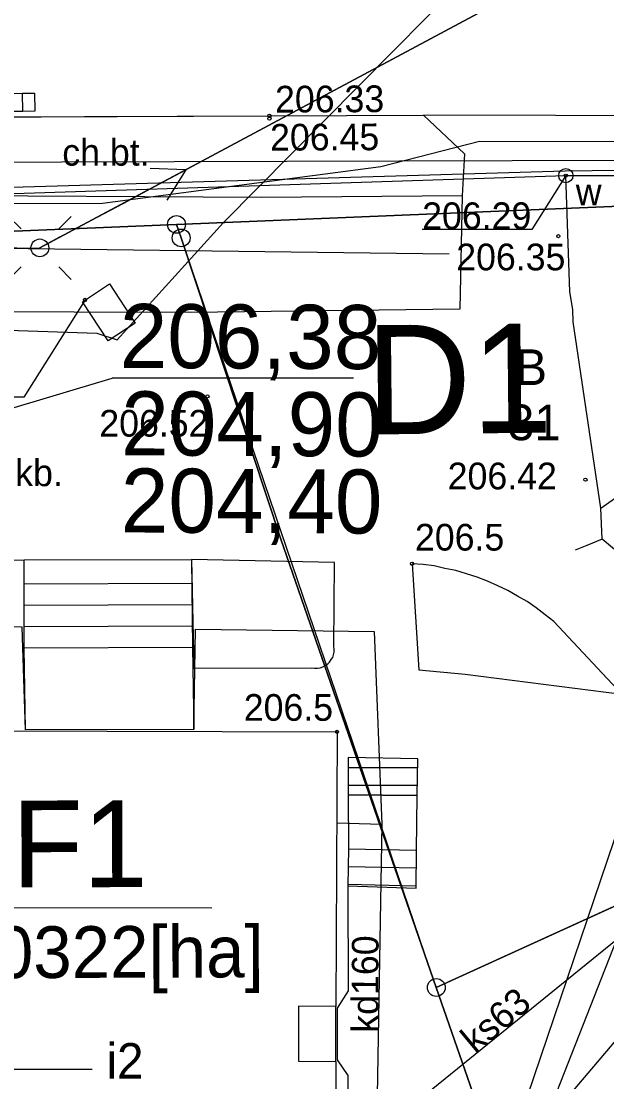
# Model space of a CAD drawing. Extents: x 6512606 to 6513006, y 6022524 to 6022728.
# Drawn here: x 6512750.51 to 6512766.96, y 6022649.64 to 6022679.43 of the extents above; entities that cross this region are included whole.
import ezdxf

# ---------------------------------------------------------------- set-up
doc = ezdxf.new("R2010")
doc.units = 0
for name, color, linetype in [('20', 7, 'Continuous'), ('202-punkt graniczny', 7, 'Continuous'), ('210-oznaczenie konturu użytku gruntowego', 7, 'Continuous'), ('211-numer działki ewidencyjnej', 7, 'Continuous'), ('216-obręb ewidencyjny', 7, 'Continuous'), ('218-kontur użytku gruntowego', 7, 'Continuous'), ('219-działka ewidencyjna', 7, 'Continuous'), ('312-budynek ewidencyjny', 7, 'Continuous'), ('312-oznaczenie budynku ewidencyjnego-Atr117', 7, 'Continuous'), ('352-schody', 7, 'Continuous'), ('4', 7, 'Continuous'), ('chodnik', 7, 'Continuous'), ('chodnik (powierzchnia)', 7, 'Continuous'), ('chodnik (powierzchnia)-Atr17', 7, 'Continuous'), ('chodnik-Atr17', 7, 'Continuous'), ('Default', 7, 'Continuous'), ('inny obiekt zagospodarowania terenu', 7, 'Continuous'), ('jezdnia (powierzchnia)', 7, 'Continuous'), ('komora podziemna - przewód kanalizacyjny (powierzchnia)', 7, 'Continuous'), ('kratka ściekowa (punkt)', 7, 'Continuous'), ('krawężnik (linia)', 7, 'Continuous'), ('latarnia na słupie lub maszcie (punkt)', 7, 'Continuous'), ('Level 47', 7, 'Continuous'), ('maxp_inst_wodociągowa', 7, 'Continuous'), ('maxp_opisy', 7, 'Continuous'), ('pikieta sztuczna', 7, 'Continuous'), ('pikieta sztuczna-Atr2', 7, 'Continuous'), ('przewód elektroenergetyczny (linia)', 7, 'Continuous'), ('przewód elektroenergetyczny niskiego napięcia (linia)', 7, 'Continuous'), ('przewód elektroenergetyczny niskiego napięcia (linia) - symbol', 7, 'Continuous'), ('przewód gazowy (linia)', 7, 'Continuous'), ('przewód kanalizacyjny (linia)', 7, 'Continuous'), ('przewód kanalizacyjny (linia)-Atr1', 7, 'Continuous'), ('przewód wodociągowy (linia)', 7, 'Continuous'), ('punkt o określonej wysokości (sieć kanalizacyjna)', 7, 'Continuous'), ('punkt o określonej wysokości (sieć kanalizacyjna)-Atr2', 7, 'Continuous'), ('punkt o określonej wysokości (sieć wodociągowa)', 7, 'Continuous'), ('punkt o określonej wysokości (sieć wodociągowa)-Atr2', 7, 'Continuous'), ('punkt wysokościowy naturalny', 7, 'Continuous'), ('punkt wysokościowy naturalny-Atr2', 7, 'Continuous'), ('punkt wysokościowy sztuczny', 7, 'Continuous'), ('punkt wysokościowy sztuczny-Atr2', 7, 'Continuous'), ('schody w ciągu komunikacyjnym', 7, 'Continuous'), ('słup (punkt)', 7, 'Continuous'), ('zasuwa - siec wodociągowa (punkt)', 7, 'Continuous'), ('zasuwa - siec wodociągowa (punkt)-Atr17', 7, 'Continuous')]:
    doc.layers.add(name, color=color, linetype=linetype)

# ---------------------------------------------------------------- blocks, each defined once
blk = doc.blocks.new('202')
at = {"layer": 'Default'}
blk.add_circle((0, 0), 2.5, dxfattribs=at)
blk = doc.blocks.new('PE04')
at = {"layer": 'Default'}
for p, q in [((46.5, 0), (37.84, 5)), ((6.5, 0), (0, 0)), ((6.5, 0), (16.5, 0)), ((16.5, 0), (26.5, 0)), ((26.5, 0), (36.5, 0)), ((36.5, 0), (46.5, 0)), ((46.5, 0), (37.84, -5)), ((46.5, 0), (50, 0))]:
    blk.add_line(p, q, dxfattribs=at)
blk = doc.blocks.new('US05')
at = {"layer": 'Default'}
for p, q in [((-5.25, -2.5), (-5.25, 2.5)), ((-5.25, 2.5), (-1.75, 2.5)), ((-1.75, -2.5), (-1.75, 2.5)), ((-1.75, 2.5), (1.75, 2.5)), ((1.75, -2.5), (1.75, 2.5)), ((1.75, 2.5), (5.25, 2.5)), ((5.25, -2.5), (5.25, 2.5)), ((-5.25, -2.5), (-1.75, -2.5)), ((-1.75, -2.5), (1.75, -2.5)), ((1.75, -2.5), (5.25, -2.5))]:
    blk.add_line(p, q, dxfattribs=at)
blk = doc.blocks.new('SM011')
at = {"layer": 'Default'}
for p, q in [((-5.3, 5.31), (-8.83, 8.84)), ((5.31, 5.31), (8.84, 8.84)), ((-5.3, -5.3), (-8.83, -8.83)), ((5.31, -5.3), (8.84, -8.83))]:
    blk.add_line(p, q, dxfattribs=at)
blk = doc.blocks.new('SM04')
at = {"layer": 'Default'}
blk.add_circle((0, 0), 2.5, dxfattribs=at)
blk = doc.blocks.new('PW02')
at = {"layer": 'Default'}
blk.add_circle((0, 0), 0.45, dxfattribs=at)
blk = doc.blocks.new('PW01')
at = {"layer": 'Default'}
blk.add_circle((0, 0), 0.45, dxfattribs=at)
blk = doc.blocks.new('US25')
at = {"layer": 'Default'}
blk.add_circle((0, 0), 2, dxfattribs=at)

msp = doc.modelspace()

# ---------------------------------------------------------------- linework, layer by layer
at = {"layer": '20'}
for p in [(6512742.779, 6022666.315), (6512759.846, 6022669.403)]:
    msp.add_line(p, (6512753.062, 6022669.403), dxfattribs=at)
at = {"layer": '216-obręb ewidencyjny'}
for points in [[(6512688.62, 6022674.91), (6512702.58, 6022674.18), (6512725.78, 6022672.95), (6512730.35, 6022672.71), (6512735.76, 6022672.94), (6512745.51, 6022673.33), (6512754.87, 6022673.72), (6512768.24, 6022674.27), (6512785.56, 6022674.74), (6512790.49, 6022674.74), (6512796.96, 6022674.74), (6512801.96, 6022670.34), (6512828.67, 6022670.98), (6512833.61, 6022675.02), (6512836.69, 6022675.17), (6512851.94, 6022675.93)], [(6512852.25, 6022608.25), (6512838.47, 6022634.29), (6512825.37, 6022649.66), (6512810.18, 6022663.28), (6512801.96, 6022670.34), (6512796.96, 6022674.74), (6512790.49, 6022674.74), (6512785.56, 6022674.74), (6512768.24, 6022674.27), (6512754.87, 6022673.72), (6512745.51, 6022673.33), (6512735.76, 6022672.94), (6512730.35, 6022672.71), (6512725.78, 6022672.95), (6512702.575, 6022674.177)]]:
    msp.add_lwpolyline(points, dxfattribs=at)
at = {"layer": '218-kontur użytku gruntowego'}
for points in [[(6512768.24, 6022674.27), (6512754.87, 6022673.72)], [(6512754.87, 6022673.72), (6512768.24, 6022674.27)], [(6512754.87, 6022673.72), (6512745.51, 6022673.33)], [(6512745.51, 6022673.33), (6512754.87, 6022673.72)], [(6512755, 6022673.34), (6512754.87, 6022673.72)], [(6512754.87, 6022673.72), (6512755, 6022673.34)], [(6512757.8, 6022664.88), (6512755, 6022673.34)], [(6512755, 6022673.34), (6512757.8, 6022664.88)], [(6512762.17, 6022652.29), (6512757.8, 6022664.88)], [(6512757.8, 6022664.88), (6512762.17, 6022652.29)], [(6512762.17, 6022652.29), (6512777.42, 6022659.24)], [(6512776.04, 6022658.61), (6512762.17, 6022652.29)], [(6512763.41, 6022648.71), (6512762.17, 6022652.29)], [(6512762.17, 6022652.29), (6512763.41, 6022648.71)]]:
    msp.add_lwpolyline(points, dxfattribs=at)
at = {"layer": '219-działka ewidencyjna'}
for points in [[(6512768.24, 6022674.27), (6512754.87, 6022673.72)], [(6512754.87, 6022673.72), (6512745.51, 6022673.33)], [(6512754.87, 6022673.72), (6512755, 6022673.34)], [(6512762.17, 6022652.29), (6512755, 6022673.34)], [(6512777.42, 6022659.24), (6512762.17, 6022652.29)], [(6512763.41, 6022648.71), (6512762.17, 6022652.29)]]:
    msp.add_lwpolyline(points, dxfattribs=at)
at = {"layer": '312-budynek ewidencyjny'}
for points in [[(6512746.45, 6022659.51), (6512759.38, 6022659.47)], [(6512759.38, 6022659.47), (6512759.35, 6022651.76)], [(6512759.35, 6022651.76), (6512758.3, 6022651.77)], [(6512758.3, 6022651.77), (6512758.3, 6022650.22)], [(6512758.3, 6022650.22), (6512759.35, 6022650.21)], [(6512759.35, 6022650.21), (6512759.3, 6022634.91)]]:
    msp.add_lwpolyline(points, dxfattribs=at)
at = {"layer": '352-schody'}
for p, q in [((6512750.59, 6022664.3), (6512755.29, 6022664.31)), ((6512750.59, 6022661.82), (6512750.59, 6022664.3)), ((6512755.29, 6022664.31), (6512755.32, 6022661.85)), ((6512755.3, 6022663.64), (6512750.59, 6022663.62)), ((6512755.31, 6022663.04), (6512750.59, 6022663.02)), ((6512755.31, 6022662.44), (6512750.59, 6022662.42)), ((6512755.32, 6022661.84), (6512750.59, 6022661.82)), ((6512750.63, 6022659.53), (6512750.59, 6022661.82)), ((6512755.32, 6022661.85), (6512755.36, 6022659.54)), ((6512755.36, 6022659.54), (6512750.63, 6022659.53)), ((6512759.35, 6022651.76), (6512758.3, 6022651.77)), ((6512758.3, 6022651.77), (6512758.3, 6022650.22)), ((6512759.35, 6022650.21), (6512759.35, 6022651.76)), ((6512758.3, 6022650.22), (6512759.35, 6022650.21))]:
    msp.add_line(p, q, dxfattribs=at)
at = {"layer": '4'}
for points in [[(6512768.24, 6022674.27), (6512754.87, 6022673.72)], [(6512754.87, 6022673.72), (6512745.51, 6022673.33)], [(6512754.87, 6022673.72), (6512755, 6022673.34)], [(6512762.17, 6022652.29), (6512755, 6022673.34)], [(6512777.42, 6022659.24), (6512762.17, 6022652.29)], [(6512763.41, 6022648.71), (6512762.17, 6022652.29)]]:
    msp.add_lwpolyline(points, dxfattribs=at)
at = {"layer": 'chodnik'}
for points in [[(6512769.23, 6022676.77), (6512761.81, 6022676.79), (6512762.96, 6022675.7), (6512762.9, 6022674.52), (6512762.83, 6022671.34), (6512755.26, 6022671.25), (6512745.44, 6022671.27)], [(6512748.06, 6022664.24), (6512750.59, 6022664.3)], [(6512759.68, 6022655.15), (6512759.69, 6022652.2), (6512759.38, 6022651.71), (6512759.38, 6022650.26), (6512759.68, 6022649.82), (6512759.66, 6022639.42)]]:
    msp.add_lwpolyline(points, dxfattribs=at)
at = {"layer": 'chodnik (powierzchnia)'}
msp.add_lwpolyline([(6512747.08, 6022676.73), (6512757.48, 6022676.77), (6512761.81, 6022676.79), (6512762.96, 6022675.7), (6512762.9, 6022674.52), (6512757.26, 6022674.48), (6512747.4, 6022674.53)], dxfattribs=at)
for points in [[(6512759.3, 6022661.71), (6512759.3, 6022661.79), (6512759.29, 6022661.87), (6512759.31, 6022664.23), (6512755.29, 6022664.31), (6512755.36, 6022661.26), (6512758.67, 6022661.27), (6512758.75, 6022661.26), (6512758.83, 6022661.26), (6512758.91, 6022661.27), (6512758.98, 6022661.3), (6512759.05, 6022661.33), (6512759.12, 6022661.38), (6512759.17, 6022661.43), (6512759.22, 6022661.5), (6512759.26, 6022661.56), (6512759.28, 6022661.63)], [(6512762.98, 6022661.09), (6512767.38, 6022660.53), (6512765.47, 6022662.57), (6512765.23, 6022662.76), (6512764.98, 6022662.95), (6512764.72, 6022663.13), (6512764.45, 6022663.28), (6512764.18, 6022663.44), (6512763.9, 6022663.57), (6512763.61, 6022663.7), (6512763.32, 6022663.81), (6512763.02, 6022663.91), (6512762.72, 6022664), (6512762.41, 6022664.06), (6512762.11, 6022664.13), (6512761.8, 6022664.17), (6512761.49, 6022664.19), (6512761.68, 6022661.21)]]:
    msp.add_lwpolyline(points, close=True, dxfattribs=at)
at = {"layer": 'Default'}
msp.add_line((6512747.5, 6022650), (6512752.5, 6022650), dxfattribs=at)
at = {"layer": 'inny obiekt zagospodarowania terenu'}
msp.add_lwpolyline([(6512746.25, 6022673.1), (6512762.53, 6022672.89)], dxfattribs=at)
at = {"layer": 'jezdnia (powierzchnia)'}
msp.add_lwpolyline([(6512707.08, 6022677.87), (6512714.85, 6022677.5), (6512727.62, 6022676.91), (6512733.49, 6022676.74), (6512737.49, 6022676.65), (6512740.34, 6022676.65), (6512746.78, 6022676.72), (6512757.48, 6022676.77)], dxfattribs=at)
at = {"layer": 'komora podziemna - przewód kanalizacyjny (powierzchnia)'}
msp.add_lwpolyline([(6512752.95, 6022670.45), (6512752.23, 6022671.55), (6512752.99, 6022672.05), (6512753.71, 6022670.95)], close=True, dxfattribs=at)
at = {"layer": 'krawężnik (linia)'}
for points in [[(6512707.08, 6022677.87), (6512714.85, 6022677.5), (6512727.62, 6022676.91), (6512733.49, 6022676.74), (6512737.49, 6022676.65), (6512740.34, 6022676.65), (6512746.78, 6022676.72), (6512757.48, 6022676.77)], [(6512757.48, 6022676.77), (6512761.81, 6022676.79)]]:
    msp.add_lwpolyline(points, dxfattribs=at)
at = {"layer": 'maxp_opisy'}
msp.add_line((6512747.949, 6022654.543), (6512755.861, 6022654.532), dxfattribs=at)
at = {"layer": 'przewód elektroenergetyczny (linia)'}
for points in [[(6512731.37, 6022676.71), (6512731.37, 6022675.58), (6512748.46, 6022675.47), (6512780.13, 6022675.56), (6512787.87, 6022675.5)], [(6512702.569, 6022673.878), (6512710.28, 6022673.25), (6512716.66, 6022675.97), (6512746.13, 6022674.3), (6512752.79, 6022674.32), (6512760.61, 6022675.35), (6512763.38, 6022676.06), (6512798.79, 6022676.04), (6512803.06, 6022673.02), (6512807.84, 6022668.96), (6512815.24, 6022662.53), (6512819.98, 6022657.77), (6512831.6, 6022645.79), (6512834.59, 6022642.25), (6512837.06, 6022638.75), (6512840.02, 6022634.13), (6512842.26, 6022630.04), (6512846.03, 6022621.35), (6512846.58, 6022618.9), (6512847.6, 6022616.23), (6512852.12, 6022605.09)], [(6512702.603, 6022675.567), (6512731.84, 6022674.22), (6512765.79, 6022675.22), (6512787.87, 6022675.5)], [(6512759.34, 6022638.24), (6512761.23, 6022638.35), (6512771.78, 6022665.17)]]:
    msp.add_lwpolyline(points, dxfattribs=at)
at = {"layer": 'przewód elektroenergetyczny niskiego napięcia (linia)'}
for points in [[(6512751.03, 6022673.06), (6512782.09, 6022689.68)], [(6512782.09, 6022689.68), (6512751.03, 6022673.06)], [(6512719.56, 6022672.79), (6512751.03, 6022673.06)]]:
    msp.add_lwpolyline(points, dxfattribs=at)
at = {"layer": 'przewód gazowy (linia)'}
msp.add_lwpolyline([(6512759.32, 6022643.31), (6512762.68, 6022643.19), (6512770.72, 6022666.88)], dxfattribs=at)
at = {"layer": 'przewód kanalizacyjny (linia)'}
for points in [[(6512756.19, 6022673.77), (6512766.65, 6022684.34)], [(6512753.2, 6022670.48), (6512756.19, 6022673.77)], [(6512716.83, 6022672.25), (6512720.83, 6022672.11), (6512730.47, 6022671.7), (6512737.04, 6022671.58), (6512738.87, 6022671.48), (6512744.52, 6022671.09), (6512750.15, 6022670.75), (6512752.63, 6022670.67), (6512753.2, 6022670.48)], [(6512750.63, 6022659.53), (6512750.53, 6022662.41), (6512746.52, 6022662.45), (6512746.43, 6022659.54), (6512745.45, 6022659.51), (6512745.46, 6022656.91), (6512745.52, 6022641.51), (6512745.53, 6022639.13), (6512748.39, 6022633.94), (6512759.09, 6022633.91), (6512760.48, 6022633.91), (6512760.44, 6022639.05)], [(6512755.36, 6022659.54), (6512755.4, 6022662.35), (6512760.42, 6022662.29), (6512760.64, 6022656.88), (6512760.38, 6022641.64), (6512760.44, 6022639.05)], [(6512761.18, 6022648.73), (6512774.9, 6022659.84), (6512776.9, 6022659.48)], [(6512759.37, 6022656.91), (6512760.64, 6022656.88)]]:
    msp.add_lwpolyline(points, dxfattribs=at)
at = {"layer": 'przewód wodociągowy (linia)'}
for points in [[(6512702.579, 6022674.359), (6512731.63, 6022673.98), (6512765.81, 6022675.09), (6512780.05, 6022675.09), (6512787.64, 6022675.26)], [(6512766.79, 6022665.75), (6512766.02, 6022670.98), (6512766.01, 6022671.33), (6512765.92, 6022671.83), (6512765.81, 6022675.09)], [(6512766.83, 6022664.88), (6512766.79, 6022665.75), (6512769.16, 6022667.43)], [(6512779.64, 6022655.03), (6512779.17, 6022655.38), (6512774.3, 6022659.21), (6512767.99, 6022663.91), (6512766.83, 6022664.88), (6512766.4, 6022664.7), (6512766.07, 6022664.57)], [(6512759.39, 6022645.33), (6512762.57, 6022645.33), (6512773.55, 6022658.26), (6512774.3, 6022659.21)]]:
    msp.add_lwpolyline(points, dxfattribs=at)
at = {"layer": 'punkt o określonej wysokości (sieć kanalizacyjna)-Atr2'}
msp.add_lwpolyline([(6512752.3, 6022671.6), (6512750.58, 6022668.87), (6512747.445, 6022668.87)], dxfattribs=at)
at = {"layer": 'punkt o określonej wysokości (sieć wodociągowa)-Atr2'}
msp.add_lwpolyline([(6512765.81, 6022675.09), (6512764.85, 6022673.58), (6512761.773, 6022673.58)], dxfattribs=at)
at = {"layer": 'schody w ciągu komunikacyjnym'}
for points in [[(6512759.69, 6022658.75), (6512759.69, 6022657.7), (6512761.63, 6022657.68), (6512761.65, 6022658.71)], [(6512761.6, 6022655.08), (6512761.61, 6022656.14), (6512761.63, 6022657.68), (6512759.69, 6022657.7), (6512759.7, 6022656.19), (6512759.68, 6022655.15)]]:
    msp.add_lwpolyline(points, close=True, dxfattribs=at)
for points in [[(6512759.69, 6022658.47), (6512761.645, 6022658.47)], [(6512759.69, 6022657.97), (6512761.636, 6022657.97)], [(6512759.7, 6022656.188), (6512761.61, 6022656.147)], [(6512759.69, 6022655.688), (6512761.605, 6022655.647)], [(6512759.681, 6022655.188), (6512761.601, 6022655.147)]]:
    msp.add_lwpolyline(points, dxfattribs=at)

# ---------------------------------------------------------------- block references
at = {"layer": '202-punkt graniczny', "xscale": 0.1, "yscale": 0.10000000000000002}
for p in [(6512754.87, 6022673.72), (6512755, 6022673.34), (6512762.17, 6022652.29)]:
    msp.add_blockref('202', p, dxfattribs=at)
at = {"layer": 'kratka ściekowa (punkt)', "xscale": 0.10000000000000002, "yscale": 0.09999999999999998, "rotation": 0.807}
msp.add_blockref('US05', (6512750.37, 6022677.15), dxfattribs=at)
at = {"layer": 'latarnia na słupie lub maszcie (punkt)', "xscale": 0.1, "yscale": 0.10000000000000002}
msp.add_blockref('SM011', (6512751.03, 6022673.06), dxfattribs=at)
at = {"layer": 'pikieta sztuczna', "xscale": 0.1, "yscale": 0.10000000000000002}
for p in [(6512765.6, 6022673.39), (6512755.74, 6022668.89), (6512766.36, 6022666.55)]:
    msp.add_blockref('PW01', p, dxfattribs=at)
at = {"layer": 'przewód elektroenergetyczny niskiego napięcia (linia) - symbol'}
for xscale, yscale, rotation in [(0.10000000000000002, 0.1, 28.151), (0.1, 0.10000000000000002, -179.50800000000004)]:
    msp.add_blockref('PE04', (6512751.03, 6022673.06), dxfattribs=dict(at, xscale=xscale, yscale=yscale, rotation=rotation))
at = {"layer": 'punkt o określonej wysokości (sieć kanalizacyjna)', "xscale": 0.1, "yscale": 0.10000000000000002}
msp.add_blockref('PW01', (6512752.3, 6022671.6), dxfattribs=at)
at = {"layer": 'punkt o określonej wysokości (sieć wodociągowa)', "xscale": 0.1, "yscale": 0.10000000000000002}
msp.add_blockref('PW01', (6512765.81, 6022675.09), dxfattribs=at)
at = {"layer": 'punkt wysokościowy naturalny', "xscale": 0.1, "yscale": 0.10000000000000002}
for p in [(6512761.49, 6022664.19), (6512759.38, 6022659.47)]:
    msp.add_blockref('PW01', p, dxfattribs=at)
at = {"layer": 'punkt wysokościowy sztuczny', "xscale": 0.1, "yscale": 0.10000000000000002}
for p in [(6512757.48, 6022676.77), (6512757.48, 6022676.69)]:
    msp.add_blockref('PW02', p, dxfattribs=at)
at = {"layer": 'słup (punkt)', "xscale": 0.1, "yscale": 0.10000000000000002}
msp.add_blockref('SM04', (6512751.03, 6022673.06), dxfattribs=at)
at = {"layer": 'zasuwa - siec wodociągowa (punkt)', "xscale": 0.1, "yscale": 0.10000000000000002}
msp.add_blockref('US25', (6512765.81, 6022675.09), dxfattribs=at)

# ---------------------------------------------------------------- texts
at = {"layer": '210-oznaczenie konturu użytku gruntowego'}
msp.add_text('B', height=1, dxfattribs=at).set_placement((6512764.39, 6022669.21))
at = {"layer": '211-numer działki ewidencyjnej'}
msp.add_text('31', height=1, dxfattribs=at).set_placement((6512764.18, 6022667.66))
at = {"layer": '312-oznaczenie budynku ewidencyjnego-Atr117'}
msp.add_text('i2', height=1, dxfattribs=at).set_placement((6512752.902, 6022649.73))
at = {"layer": '4'}
msp.add_text('31', height=1, dxfattribs=at).set_placement((6512764.18, 6022667.66))
at = {"layer": 'chodnik (powierzchnia)-Atr17'}
msp.add_text('ch.bt.', height=0.75, dxfattribs=at).set_placement((6512751.66, 6022675.37))
at = {"layer": 'chodnik-Atr17'}
msp.add_text('ch.kb.', height=0.75, dxfattribs=at).set_placement((6512749, 6022666.37))
at = {"layer": 'Level 47'}
for s, p in [('206,38', (6512753.271, 6022669.691)), ('204,90', (6512753.311, 6022667.236)), ('204,40', (6512753.301, 6022665.071))]:
    msp.add_text(s, height=1.7971, rotation=359.7281, dxfattribs=at).set_placement(p)
at = {"layer": 'maxp_inst_wodociągowa'}
msp.add_text('D1', height=3.0671, rotation=0.5777, dxfattribs=at).set_placement((6512760.205, 6022667.82))
at = {"layer": 'maxp_opisy'}
for s, height, p in [('F1', 2.4386, (6512750.251, 6022655.099)), ('0,0322[ha]', 1.4515, (6512748.148, 6022652.547))]:
    msp.add_text(s, height=height, rotation=0.1859, dxfattribs=at).set_placement(p)
at = {"layer": 'pikieta sztuczna-Atr2'}
for s, p in [('206.35', (6512762.73, 6022672.43)), ('206.52', (6512752.7, 6022667.76)), ('206.42', (6512762.49, 6022666.28))]:
    msp.add_text(s, height=0.75, dxfattribs=at).set_placement(p)
at = {"layer": 'przewód kanalizacyjny (linia)-Atr1'}
for s, rotation, p in [('kd160', 89.812, (6512760.54, 6022651.02)), ('ks63', 39.806, (6512763.26, 6022650.41))]:
    msp.add_text(s, height=0.75, rotation=rotation, dxfattribs=at).set_placement(p)
at = {"layer": 'punkt o określonej wysokości (sieć wodociągowa)-Atr2'}
msp.add_text('206.29', height=0.75, dxfattribs=at).set_placement((6512761.773, 6022673.588))
at = {"layer": 'punkt wysokościowy naturalny-Atr2'}
for p in [(6512761.57, 6022664.56), (6512756.76, 6022659.78)]:
    msp.add_text('206.5', height=0.75, dxfattribs=at).set_placement(p)
at = {"layer": 'punkt wysokościowy sztuczny-Atr2'}
for s, p in [('206.33', (6512757.64, 6022676.86)), ('206.45', (6512757.5, 6022675.79))]:
    msp.add_text(s, height=0.75, rotation=0.264, dxfattribs=at).set_placement(p)
at = {"layer": 'zasuwa - siec wodociągowa (punkt)-Atr17'}
msp.add_text('w', height=0.75, dxfattribs=at).set_placement((6512766.09, 6022674.26))

doc.saveas('drawing.dxf')
